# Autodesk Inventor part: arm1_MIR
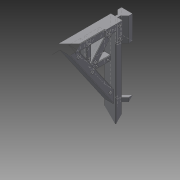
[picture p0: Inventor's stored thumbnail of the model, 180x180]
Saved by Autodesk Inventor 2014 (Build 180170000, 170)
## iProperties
Created: 2013-07
Part Number: arm1_MIR
Material: Generic
Document SubType Name: Modeling
Designer: Brent J. Rosenburgh
Density: 1 g/cm^3
Appearance: Default
Author: Brent J. Rosenburgh
d0: 8.000 mm
d1: 119.000 mm
d2: 0.00 deg
d3: 19.000 mm
d4: 0.00 deg
d5: 14.000 mm
d6: 0.00 deg
d7: 12.000 mm
d8: 0.00 deg
d9: 10.000 mm
d10: 0.00 deg
d11: 8.000 mm
d12: 0.00 deg
d13: 1.000 mm
d14: 0.00 deg
d15: 1.000 mm
d16: 0.00 deg
d17: 1.000 mm
d18: 0.00 deg
d19: 1.000 mm
d20: 0.00 deg
d21: 1.000 mm
d22: 0.00 deg
d23: 1.000 mm
d24: 0.00 deg
d25: 8.000 mm
d26: 0.00 deg
d27: 8.000 mm
d30: 5.000 mm
d33: 4.000 mm
d34: 0.00 deg
d35: 6.000 mm
d36: 4.000 mm
d37: 0.00 deg
d38: 3.000 mm
d41: 1.000 mm
d44: 0.600 mm
d47: 0.600 mm
d50: 1.850 mm
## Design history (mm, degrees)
derived "arm1.ipt"
  sketch "Sketch1"
    geometry: L1 (7, 5)-(-7, 5) reference; L2 (-7, 5)-(-7, 0) reference; L3 (-7, 0)-(-2, -5) reference; L4 (7, 5)-(7, 0) reference; L5 (7, 0)-(2, -5) reference; L6 (2, -5)-(1.627, -5.373) reference; L7 (1.627, -5.373)-(1.627, -8.541) reference; L8 (-2, -5)-(-1.627, -5.373) reference; L9 (-1.627, -5.373)-(-1.627, -8.541) reference; L10 (-1.627, -8.541)-(-7, -8.541) reference; L11 (1.627, -8.541)-(7, -8.541) reference; L12 (7, -8.541)-(7, -16.541) reference; L13 (7, -16.541)-(-7, -16.541) reference; L14 (-7, -16.541)-(-7, -8.541) reference; 1 further point
  sketch "Sketch2"
    geometry: L1 (0, 8)-(119, 8) reference; L2 (30, 8)-(89, 8) reference; L3 (89, 8)-(89, 24) reference; L4 (89, 24)-(30, 24) reference; L5 (30, 24)-(30, 8) reference; 1 further point
  sketch "Sketch3"
    geometry: L1 (0, 0)-(-119, 0) reference; L2 (0, 8)-(-119, 8) reference; L3 (-119, 0)-(-119, -80) reference; L4 (-119, -80)-(-111, -80) reference; L5 (-111, -80)-(-111, 0) reference; 1 further point
  sketch "Sketch4"
    geometry: L1 (0, 0)-(-111, 0) reference; L2 (-111, 0)-(-111, -80) reference; L3 (-111, -56)-(-30, 0) reference; L4 (-46, 0)-(-111, -44.938) reference; 1 further point
  sketch "Sketch5"
    geometry: L1 (-111, -44.938)-(-46, 0) reference; L2 (-105, 0)-(-78.5, -22.469) reference; L3 (-111, -6)-(-85.703, -27.449) reference; L4 (-46, 0)-(-111, 0) reference; L5 (-111, 0)-(-111, -44.938) reference; 1 further point
  sketch "Sketch6"
    geometry: L1 (-81.627, 3)-(-75.061, 3) reference; L2 (-75.061, 3)-(-75.061, -25.469) reference; L3 (-75.061, -25.469)-(-81.627, -25.469) reference; L4 (-81.627, -25.469)-(-81.627, 3) reference; L5 (-113, -24.592)-(-81.627, -24.592) reference; L6 (-81.627, -24.592)-(-81.627, -30.232) reference; L7 (-81.627, -30.232)-(-113, -30.232) reference; L8 (-113, -30.232)-(-113, -24.592) reference; 1 further point
  sketch "Sketch7"
    geometry: L1 (0, 8)-(119, 8) reference; L2 (119, 8)-(119, -80) reference; L3 (111, -80)-(111, 0) reference; L4 (0, 0)-(111, 0) reference; L5 (97, 0)-(97, 8) reference; L6 (111, -14)-(119, -14) reference; 1 further point
  sketch "Sketch8"
    geometry: L1 (103.938, -47.474)-(105.67, -46.474) reference; L2 (105.67, -46.474)-(105.67, -44.474) reference; L3 (105.67, -44.474)-(103.938, -43.474) reference; L4 (103.938, -43.474)-(102.206, -44.474) reference; L5 (102.206, -44.474)-(102.206, -46.474) reference; L6 (102.206, -46.474)-(103.938, -47.474) reference; L7 (45, -7)-(46.732, -6) reference; L8 (46.732, -6)-(46.732, -4) reference; L9 (46.732, -4)-(45, -3) reference; L10 (45, -3)-(43.268, -4) reference; L11 (43.268, -4)-(43.268, -6) reference; L12 (43.268, -6)-(45, -7) reference; L13 (78.5, -29.888)-(80.232, -28.888) reference; L14 (80.232, -28.888)-(80.232, -26.888) reference; L15 (80.232, -26.888)-(78.5, -25.888) reference; L16 (78.5, -25.888)-(76.768, -26.888) reference; L17 (76.768, -26.888)-(76.768, -28.888) reference; L18 (76.768, -28.888)-(78.5, -29.888) reference; 4 further points
    constraints: 3 other
  sketch "Sketch9"
    geometry: L1 (101, 2)-(102.732, 3) reference; L2 (102.732, 3)-(102.732, 5) reference; L3 (102.732, 5)-(101, 6) reference; L4 (101, 6)-(99.268, 5) reference; L5 (99.268, 5)-(99.268, 3) reference; L6 (99.268, 3)-(101, 2) reference; L7 (115, -12)-(116.732, -11) reference; L8 (116.732, -11)-(116.732, -9) reference; L9 (116.732, -9)-(115, -8) reference; L10 (115, -8)-(113.268, -9) reference; L11 (113.268, -9)-(113.268, -11) reference; L12 (113.268, -11)-(115, -12) reference; L13 (115, 2)-(116.732, 3) reference; L14 (116.732, 3)-(116.732, 5) reference; L15 (116.732, 5)-(115, 6) reference; L16 (115, 6)-(113.268, 5) reference; L17 (113.268, 5)-(113.268, 3) reference; L18 (113.268, 3)-(115, 2) reference; 4 further points
    constraints: 3 other
  sketch "Sketch10"
    geometry: L1 (106, -7)-(107.732, -6) reference; L2 (107.732, -6)-(107.732, -4) reference; L3 (107.732, -4)-(106, -3) reference; L4 (106, -3)-(104.268, -4) reference; L5 (104.268, -4)-(104.268, -6) reference; L6 (104.268, -6)-(106, -7) reference; L7 (85.703, -24)-(87.435, -23) reference; L8 (87.435, -23)-(87.435, -21) reference; L9 (87.435, -21)-(85.703, -20) reference; L10 (85.703, -20)-(83.971, -21) reference; L11 (83.971, -21)-(83.971, -23) reference; L12 (83.971, -23)-(85.703, -24) reference; 3 further points
    constraints: 2 other
  sketch "Sketch11"
    geometry: L1 (79.811, -18)-(79.155, -16.865) reference; L2 (79.155, -16.865)-(77.845, -16.865) reference; L3 (77.845, -16.865)-(77.189, -18) reference; L4 (77.189, -18)-(77.845, -19.135) reference; L5 (77.845, -19.135)-(79.155, -19.135) reference; L6 (79.155, -19.135)-(79.811, -18) reference; L7 (79.811, -4)-(79.155, -2.865) reference; L8 (79.155, -2.865)-(77.845, -2.865) reference; L9 (77.845, -2.865)-(77.189, -4) reference; L10 (77.189, -4)-(77.845, -5.135) reference; L11 (77.845, -5.135)-(79.155, -5.135) reference; L12 (79.155, -5.135)-(79.811, -4) reference; 3 further points
    constraints: 2 other
  sketch "Sketch12"
    geometry: L1 (107, -28.841)-(108.237, -28.126) reference; L2 (108.237, -28.126)-(108.237, -26.698) reference; L3 (108.237, -26.698)-(107, -25.983) reference; L4 (107, -25.983)-(105.763, -26.698) reference; L5 (105.763, -26.698)-(105.763, -28.126) reference; L6 (105.763, -28.126)-(107, -28.841) reference; L7 (92, -28.841)-(93.237, -28.126) reference; L8 (93.237, -28.126)-(93.237, -26.698) reference; L9 (93.237, -26.698)-(92, -25.983) reference; L10 (92, -25.983)-(90.763, -26.698) reference; L11 (90.763, -26.698)-(90.763, -28.126) reference; L12 (90.763, -28.126)-(92, -28.841) reference; 3 further points
    constraints: 2 other
  sketch "Sketch13"
    geometry: L1 (-14, 0)-(8, 0) reference; L2 (8, 0)-(8, 22) reference; L3 (8, 22)-(-14, 22) reference; L4 (-14, 22)-(-14, 0) reference; 1 further point
  sketch "Sketch14"
    geometry: L1 (-8.5, -9.364)-(-8.449, -15.556) reference; L2 (-8.449, -15.556)-(-4.034, -19.898) reference; L3 (-4.034, -19.898)-(2.158, -19.847) reference; L4 (2.158, -19.847)-(6.5, -15.432) reference; L5 (6.5, -15.432)-(6.449, -9.24) reference; L6 (6.449, -9.24)-(2.034, -4.898) reference; L7 (2.034, -4.898)-(-4.158, -4.949) reference; L8 (-4.158, -4.949)-(-8.5, -9.364) reference; 2 further points
    constraints: 1 other
  sketch "Sketch15"
    geometry: C1 r 3 at (-0.938, -12.335) reference; 1 further point
feature "Solid1::arm1.ipt"
tag "TaggingFeature1"
body "Solid1"
other parameters: "d0" = 10, "d0_1" = 8, "d1" = 119, "d2" = 0 deg, "d3" = 19, "d4" = 0 deg, "d5" = 14, "d6" = 0 deg, "d7" = 12, "d8" = 0 deg, "d9" = 10, "d10" = 0 deg, "d11" = 8, "d12" = 0 deg, "d13" = 1, "d14" = 0 deg, "d15" = 1, "d16" = 0 deg, "d17" = 1, "d18" = 0 deg, "d19" = 1, "d20" = 0 deg, "d21" = 1, "d22" = 0 deg, "d23" = 1, "d24" = 0 deg, "d25" = 8, "d26" = 0 deg, "d27" = 8, "d30" = 5, "d33" = 4, "d34" = 0 deg, "d35" = 6, "d36" = 4, "d37" = 0 deg, "d38" = 3, "d41" = 1, "d44" = 0.6, "d47" = 0.6, "d50" = 1.85
